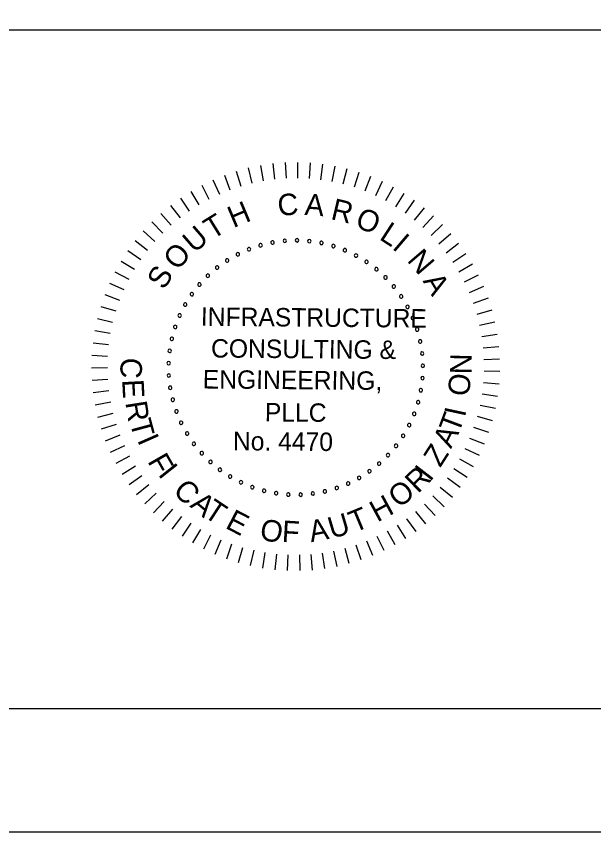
# Model space of a CAD drawing. Extents: x -125.5 to -89.4, y -5.1 to 16.9.
# Drawn here: x -100.333 to -97.992, y -5.066 to -1.761 of the extents above; entities that cross this region are included whole.
import ezdxf

# ---------------------------------------------------------------- set-up
doc = ezdxf.new("R2010")
doc.units = 0
for name, color, linetype in [('BR_BORDER LINES', 7, 'Continuous'), ('BR_TEXT', 7, 'Continuous'), ('Level 31', 7, 'Continuous')]:
    doc.layers.add(name, color=color, linetype=linetype)

msp = doc.modelspace()

# ---------------------------------------------------------------- linework, layer by layer
at = {"layer": 'BR_BORDER LINES'}
for p, q in [((-102.8989, -1.8161), (-97.5337, -1.8161)), ((-123.6994, -4.5662), (-90.0334, -4.5662))]:
    msp.add_line(p, q, dxfattribs=at)
at = {"layer": 'BR_TEXT'}
for p, q in [((-99.3925, -2.3754), (-99.3776, -2.4373)), ((-99.343, -2.3651), (-99.332, -2.4278)), ((-99.2931, -2.3579), (-99.2858, -2.4212)), ((-99.2427, -2.3538), (-99.2394, -2.4174)), ((-99.1923, -2.3527), (-99.1928, -2.4164)), ((-99.1418, -2.3548), (-99.1462, -2.4183)), ((-99.0916, -2.3599), (-99.0999, -2.423)), ((-99.0418, -2.368), (-99.0539, -2.4305)), ((-98.9925, -2.3792), (-99.0084, -2.4408)), ((-99.489, -2.4048), (-99.4667, -2.4644)), ((-99.4412, -2.3886), (-99.4226, -2.4495)), ((-98.9441, -2.3933), (-98.9637, -2.4539)), ((-98.8966, -2.4104), (-98.9199, -2.4696)), ((-99.5813, -2.4457), (-99.5519, -2.5022)), ((-99.5358, -2.4238), (-99.5099, -2.482)), ((-98.8502, -2.4303), (-98.877, -2.488)), ((-99.6253, -2.4703), (-99.5926, -2.5249)), ((-98.8051, -2.453), (-98.8354, -2.509)), ((-98.7615, -2.4785), (-98.7952, -2.5325)), ((-99.6678, -2.4975), (-99.6318, -2.55)), ((-98.7195, -2.5065), (-98.7564, -2.5584)), ((-99.7086, -2.5273), (-99.6694, -2.5775)), ((-98.6793, -2.5371), (-98.7193, -2.5866)), ((-99.7475, -2.5595), (-99.7053, -2.6072)), ((-98.6411, -2.57), (-98.684, -2.617)), ((-99.7843, -2.5941), (-99.7393, -2.6391)), ((-98.6049, -2.6052), (-98.6506, -2.6495)), ((-99.819, -2.6308), (-99.7713, -2.673)), ((-98.571, -2.6426), (-98.6193, -2.684)), ((-99.8513, -2.6695), (-99.8012, -2.7087)), ((-99.8813, -2.7102), (-99.8288, -2.7463)), ((-98.5393, -2.6819), (-98.5901, -2.7204)), ((-98.5102, -2.7232), (-98.5632, -2.7584)), ((-99.9087, -2.7526), (-99.8541, -2.7854)), ((-98.4836, -2.7661), (-98.5387, -2.798)), ((-99.9334, -2.7966), (-99.877, -2.826)), ((-99.9555, -2.842), (-99.8973, -2.8679)), ((-98.4597, -2.8105), (-98.5166, -2.839)), ((-98.4385, -2.8564), (-98.497, -2.8814)), ((-99.9747, -2.8886), (-99.9151, -2.911)), ((-98.4201, -2.9034), (-98.4801, -2.9248)), ((-99.991, -2.9364), (-99.9302, -2.9551)), ((-98.4047, -2.9515), (-98.4659, -2.9691)), ((-100.0044, -2.9851), (-99.9426, -3)), ((-98.3922, -3.0004), (-98.4544, -3.0143)), ((-100.0149, -3.0345), (-99.9522, -3.0456)), ((-98.3828, -3.05), (-98.4456, -3.0601)), ((-100.0222, -3.0844), (-99.959, -3.0917)), ((-98.3763, -3.1), (-98.4397, -3.1063)), ((-100.0266, -3.1347), (-99.963, -3.1382)), ((-98.373, -3.1504), (-98.4366, -3.1528)), ((-100.0278, -3.1852), (-99.9641, -3.1847)), ((-98.3727, -3.2009), (-98.4363, -3.1994)), ((-100.026, -3.2356), (-99.9625, -3.2313)), ((-98.3755, -3.2513), (-98.4389, -3.2459)), ((-100.0211, -3.2859), (-99.9579, -3.2777)), ((-98.3813, -3.3014), (-98.4443, -3.2922)), ((-100.0131, -3.3357), (-99.9506, -3.3237)), ((-98.3902, -3.3511), (-98.4525, -3.3381)), ((-100.0021, -3.385), (-99.9405, -3.3692)), ((-98.4021, -3.4002), (-98.4635, -3.3834)), ((-99.9882, -3.4335), (-99.9276, -3.414)), ((-98.417, -3.4484), (-98.4773, -3.4279)), ((-99.9713, -3.4811), (-99.912, -3.4579)), ((-99.9515, -3.5276), (-99.8937, -3.5008)), ((-98.4348, -3.4957), (-98.4937, -3.4715)), ((-98.4554, -3.5417), (-98.5128, -3.514)), ((-99.9289, -3.5727), (-99.8729, -3.5425)), ((-98.4789, -3.5865), (-98.5344, -3.5553)), ((-99.9037, -3.6164), (-99.8496, -3.5828)), ((-98.5049, -3.6297), (-98.5585, -3.5952)), ((-99.8758, -3.6585), (-99.8239, -3.6217)), ((-98.5336, -3.6712), (-98.5849, -3.6335)), ((-99.8454, -3.6988), (-99.7958, -3.6589)), ((-99.8126, -3.7372), (-99.7655, -3.6943)), ((-98.5648, -3.7109), (-98.6137, -3.6702)), ((-99.7775, -3.7735), (-99.7331, -3.7278)), ((-98.5983, -3.7487), (-98.6447, -3.705)), ((-99.7403, -3.8076), (-99.6988, -3.7593)), ((-98.6341, -3.7843), (-98.6777, -3.7379)), ((-99.701, -3.8393), (-99.6626, -3.7886)), ((-98.7118, -3.8487), (-98.7494, -3.7974)), ((-98.6719, -3.8177), (-98.7126, -3.7687)), ((-99.6599, -3.8687), (-99.6246, -3.8157)), ((-98.7534, -3.8772), (-98.7879, -3.8237)), ((-99.6171, -3.8954), (-99.5851, -3.8404)), ((-99.5728, -3.9195), (-99.5442, -3.8626)), ((-98.7967, -3.9032), (-98.8278, -3.8476)), ((-99.527, -3.9408), (-99.5019, -3.8823)), ((-99.48, -3.9594), (-99.4586, -3.8994)), ((-98.8877, -3.9469), (-98.9118, -3.888)), ((-98.8416, -3.9264), (-98.8692, -3.8691)), ((-99.432, -3.975), (-99.4143, -3.9138)), ((-99.3832, -3.9876), (-99.3692, -3.9255)), ((-99.0324, -3.991), (-99.0454, -3.9286)), ((-98.9833, -3.9792), (-99.0001, -3.9178)), ((-98.935, -3.9645), (-98.9555, -3.9042)), ((-99.3336, -3.9973), (-99.3234, -3.9344)), ((-99.2836, -4.0039), (-99.2772, -3.9406)), ((-99.2332, -4.0075), (-99.2307, -3.9438)), ((-99.1827, -4.0079), (-99.1841, -3.9443)), ((-99.1323, -4.0053), (-99.1376, -3.9419)), ((-99.0821, -3.9997), (-99.0913, -3.9367))]:
    msp.add_line(p, q, dxfattribs=at)
for centre, start, end in [((-99.2939, -2.6775), 10.6038, 190.6038), ((-99.2939, -2.6775), 190.6038, 10.6038), ((-99.2445, -2.6708), 5.0653, 185.0653), ((-99.2445, -2.6708), 185.0653, 5.0653), ((-99.1947, -2.6689), 359.5268, 179.5268), ((-99.1947, -2.6689), 179.5268, 359.5268), ((-99.145, -2.6718), 173.9884, 353.9884), ((-99.145, -2.6718), 353.9884, 173.9884), ((-99.0957, -2.6795), 348.4499, 168.4499), ((-99.3895, -2.705), 21.6807, 201.6807), ((-99.3895, -2.705), 201.6807, 21.6807), ((-99.3424, -2.6889), 16.1422, 196.1422), ((-99.3424, -2.6889), 196.1422, 16.1422), ((-99.0957, -2.6795), 168.4499, 348.4499), ((-99.0475, -2.6919), 162.9114, 342.9114), ((-99.0475, -2.6919), 342.9114, 162.9114), ((-99.0006, -2.709), 157.373, 337.373), ((-99.0006, -2.709), 337.373, 157.373), ((-99.4782, -2.7503), 32.7576, 212.7576), ((-99.435, -2.7255), 27.2191, 207.2191), ((-99.435, -2.7255), 207.2191, 27.2191), ((-98.9557, -2.7304), 151.8345, 331.8345), ((-98.9557, -2.7304), 331.8345, 151.8345), ((-99.5188, -2.7792), 38.2961, 218.2961), ((-99.5188, -2.7792), 218.2961, 38.2961), ((-99.4782, -2.7503), 212.7576, 32.7576), ((-98.913, -2.7561), 146.2961, 326.2961), ((-98.913, -2.7561), 326.2961, 146.2961), ((-99.5564, -2.8119), 43.8345, 223.8345), ((-99.5564, -2.8119), 223.8345, 43.8345), ((-98.873, -2.7858), 140.7576, 320.7576), ((-98.873, -2.7858), 320.7576, 140.7576), ((-99.5907, -2.848), 49.373, 229.373), ((-99.5907, -2.848), 229.373, 49.373), ((-98.836, -2.8192), 135.2191, 315.2191), ((-98.836, -2.8192), 315.2191, 135.2191), ((-98.8024, -2.8561), 129.6807, 309.6807), ((-98.8024, -2.8561), 309.6807, 129.6807), ((-99.6214, -2.8873), 54.9114, 234.9114), ((-99.6214, -2.8873), 234.9114, 54.9114), ((-98.7726, -2.896), 124.1422, 304.1422), ((-98.7726, -2.896), 304.1422, 124.1422), ((-99.6481, -2.9293), 60.4499, 240.4499), ((-99.6481, -2.9293), 240.4499, 60.4499), ((-98.7467, -2.9386), 118.6038, 298.6038), ((-98.7467, -2.9386), 298.6038, 118.6038), ((-99.6706, -2.9738), 65.9884, 245.9884), ((-99.6706, -2.9738), 245.9884, 65.9884), ((-98.7251, -2.9835), 113.0653, 293.0653), ((-98.7251, -2.9835), 293.0653, 113.0653), ((-99.6888, -3.0202), 71.5268, 251.5268), ((-99.6888, -3.0202), 251.5268, 71.5268), ((-98.7079, -3.0302), 107.5268, 287.5268), ((-98.7079, -3.0302), 287.5268, 107.5268), ((-99.7024, -3.0681), 77.0653, 257.0653), ((-99.7024, -3.0681), 257.0653, 77.0653), ((-98.6953, -3.0785), 101.9884, 281.9884), ((-98.6953, -3.0785), 281.9884, 101.9884), ((-99.7113, -3.1172), 82.6038, 262.6038), ((-99.7113, -3.1172), 262.6038, 82.6038), ((-98.6874, -3.1277), 96.4499, 276.4499), ((-98.6874, -3.1277), 276.4499, 96.4499), ((-99.7154, -3.1668), 88.1422, 268.1422), ((-99.7154, -3.1668), 268.1422, 88.1422), ((-98.6843, -3.1774), 90.9114, 270.9114), ((-98.6843, -3.1774), 270.9114, 90.9114), ((-99.7147, -3.2167), 93.6807, 273.6807), ((-99.7147, -3.2167), 273.6807, 93.6807), ((-98.686, -3.2272), 85.373, 265.373), ((-98.686, -3.2272), 265.373, 85.373), ((-99.7092, -3.2662), 99.2191, 279.2191), ((-99.7092, -3.2662), 279.2191, 99.2191), ((-98.6926, -3.2766), 79.8345, 259.8345), ((-98.6926, -3.2766), 259.8345, 79.8345), ((-99.6989, -3.3149), 104.7576, 284.7576), ((-99.6989, -3.3149), 284.7576, 104.7576), ((-98.7038, -3.3251), 74.2961, 254.2961), ((-98.7038, -3.3251), 254.2961, 74.2961), ((-99.684, -3.3625), 110.2961, 290.2961), ((-99.684, -3.3625), 290.2961, 110.2961), ((-98.7197, -3.3724), 68.7576, 248.7576), ((-98.7197, -3.3724), 248.7576, 68.7576), ((-99.6646, -3.4084), 115.8345, 295.8345), ((-99.6646, -3.4084), 295.8345, 115.8345), ((-98.7401, -3.4179), 63.2191, 243.2191), ((-98.7401, -3.4179), 243.2191, 63.2191), ((-99.6408, -3.4522), 121.373, 301.373), ((-99.6408, -3.4522), 301.373, 121.373), ((-98.7647, -3.4612), 57.6807, 237.6807), ((-98.7647, -3.4612), 237.6807, 57.6807), ((-99.6129, -3.4935), 126.9114, 306.9114), ((-99.6129, -3.4935), 306.9114, 126.9114), ((-98.7934, -3.5019), 52.1422, 232.1422), ((-98.7934, -3.5019), 232.1422, 52.1422), ((-99.5812, -3.5319), 132.4499, 312.4499), ((-99.5812, -3.5319), 312.4499, 132.4499), ((-98.826, -3.5396), 46.6038, 226.6038), ((-98.826, -3.5396), 226.6038, 46.6038), ((-99.5459, -3.5671), 137.9884, 317.9884), ((-99.5459, -3.5671), 317.9884, 137.9884), ((-98.862, -3.5741), 41.0653, 221.0653), ((-98.862, -3.5741), 221.0653, 41.0653), ((-99.5074, -3.5987), 143.5268, 323.5268), ((-99.5074, -3.5987), 323.5268, 143.5268), ((-98.9012, -3.6049), 35.5268, 215.5268), ((-98.9012, -3.6049), 215.5268, 35.5268), ((-99.466, -3.6264), 149.0653, 329.0653), ((-99.466, -3.6264), 329.0653, 149.0653), ((-98.9431, -3.6317), 29.9884, 209.9884), ((-98.9431, -3.6317), 209.9884, 29.9884), ((-99.4221, -3.65), 154.6038, 334.6038), ((-99.4221, -3.65), 334.6038, 154.6038), ((-99.3761, -3.6693), 160.1422, 340.1422), ((-99.3761, -3.6693), 340.1422, 160.1422), ((-99.0338, -3.6728), 18.9114, 198.9114), ((-98.9875, -3.6545), 24.4499, 204.4499), ((-98.9875, -3.6545), 204.4499, 24.4499), ((-99.3285, -3.684), 165.6807, 345.6807), ((-99.3285, -3.684), 345.6807, 165.6807), ((-99.2797, -3.6941), 171.2191, 351.2191), ((-99.2797, -3.6941), 351.2191, 171.2191), ((-99.2302, -3.6994), 356.7576, 176.7576), ((-99.2302, -3.6994), 176.7576, 356.7576), ((-99.1803, -3.6999), 2.2961, 182.2961), ((-99.1803, -3.6999), 182.2961, 2.2961), ((-99.1307, -3.6956), 7.8345, 187.8345), ((-99.1307, -3.6956), 187.8345, 7.8345), ((-99.0817, -3.6865), 13.373, 193.373), ((-99.0817, -3.6865), 193.373, 13.373), ((-99.0338, -3.6728), 198.9114, 18.9114)]:
    msp.add_arc(centre, 0.00701, start, end, dxfattribs=at)
at = {"layer": 'Level 31'}
msp.add_lwpolyline([(-125.5328, -5.0661), (-89.5328, -5.0661), (-89.5328, 16.9339), (-125.5328, 16.9339)], close=True, dxfattribs=at)

# ---------------------------------------------------------------- texts
at = {"layer": 'BR_TEXT'}
for s, height, rotation, p in [('C', 0.0872, 4.7281, (-99.2702, -2.5703)), ('H', 0.0872, 22.7882, (-99.453, -2.6197)), ('A', 0.0872, 355.6981, (-99.1657, -2.5654)), ('R', 0.0872, 346.6681, (-99.0615, -2.5824)), ('O', 0.0872, 337.638, (-98.9637, -2.6122)), ('T', 0.0872, 31.8182, (-99.5379, -2.6674)), ('U', 0.0872, 40.8482, (-99.6112, -2.7235)), ('L', 0.0872, 327.108, (-98.8649, -2.6626)), ('I', 0.0872, 319.578, (-98.8123, -2.7005)), ('O', 0.0872, 49.8782, (-99.6782, -2.7945)), ('N', 0.0872, 310.548, (-98.7515, -2.7512)), ('S', 0.0872, 58.9083, (-99.7336, -2.8727)), ('A', 0.0872, 301.5179, (-98.6864, -2.8336)), ('INFRASTRUCTURE', 0.074771, 359.5268, (-99.585, -3.0152)), ('CONSULTING &', 0.074771, 359.5268, (-99.5437, -3.1438)), ('N', 0.0872, 89.2085, (-98.4872, -3.2124)), ('C', 0.0872, 267.025, (-99.9086, -3.1426)), ('ENGINEERING,', 0.074771, 359.5268, (-99.5773, -3.2693)), ('E', 0.0872, 273.025, (-99.9042, -3.2342)), ('O', 0.0872, 83.2085, (-98.4982, -3.3038)), ('R', 0.0872, 279.025, (-99.8914, -3.3265)), ('PLLC', 0.07477, 359.5268, (-99.3256, -3.4028)), ('T', 0.0872, 69.3954, (-98.5394, -3.4556)), ('I', 0.0872, 77.9093, (-98.5137, -3.3881)), ('T', 0.0872, 285.025, (-99.874, -3.4053)), ('A', 0.0872, 63.3954, (-98.5702, -3.516)), ('I', 0.0872, 293.7713, (-99.8443, -3.4784)), ('No. 4470', 0.07477, 359.5268, (-99.4551, -3.5197)), ('Z', 0.0872, 57.3954, (-98.6141, -3.5923)), ('F', 0.0872, 299.7713, (-99.8031, -3.5644)), ('I', 0.0872, 308.5268, (-99.761, -3.6183)), ('R', 0.0872, 44.5268, (-98.7045, -3.6973)), ('I', 0.0872, 52.3339, (-98.6551, -3.65)), ('C', 0.0872, 314.5268, (-99.7017, -3.6884)), ('O', 0.0872, 38.5268, (-98.7811, -3.7572)), ('A', 0.0872, 320.5268, (-99.6325, -3.747)), ('H', 0.0872, 28.5268, (-98.8692, -3.8132)), ('T', 0.0872, 326.5268, (-99.5781, -3.7855)), ('E', 0.0872, 332.5268, (-99.4895, -3.8332)), ('T', 0.0872, 22.5268, (-98.9624, -3.855)), ('O', 0.0872, 350.5268, (-99.3494, -3.8821)), ('A', 0.0872, 10.5268, (-99.138, -3.8929)), ('U', 0.0872, 16.5268, (-99.0541, -3.8794)), ('F', 0.0872, 356.5268, (-99.2579, -3.8912))]:
    msp.add_text(s, height=height, rotation=rotation, dxfattribs=at).set_placement(p)

doc.saveas('drawing.dxf')
